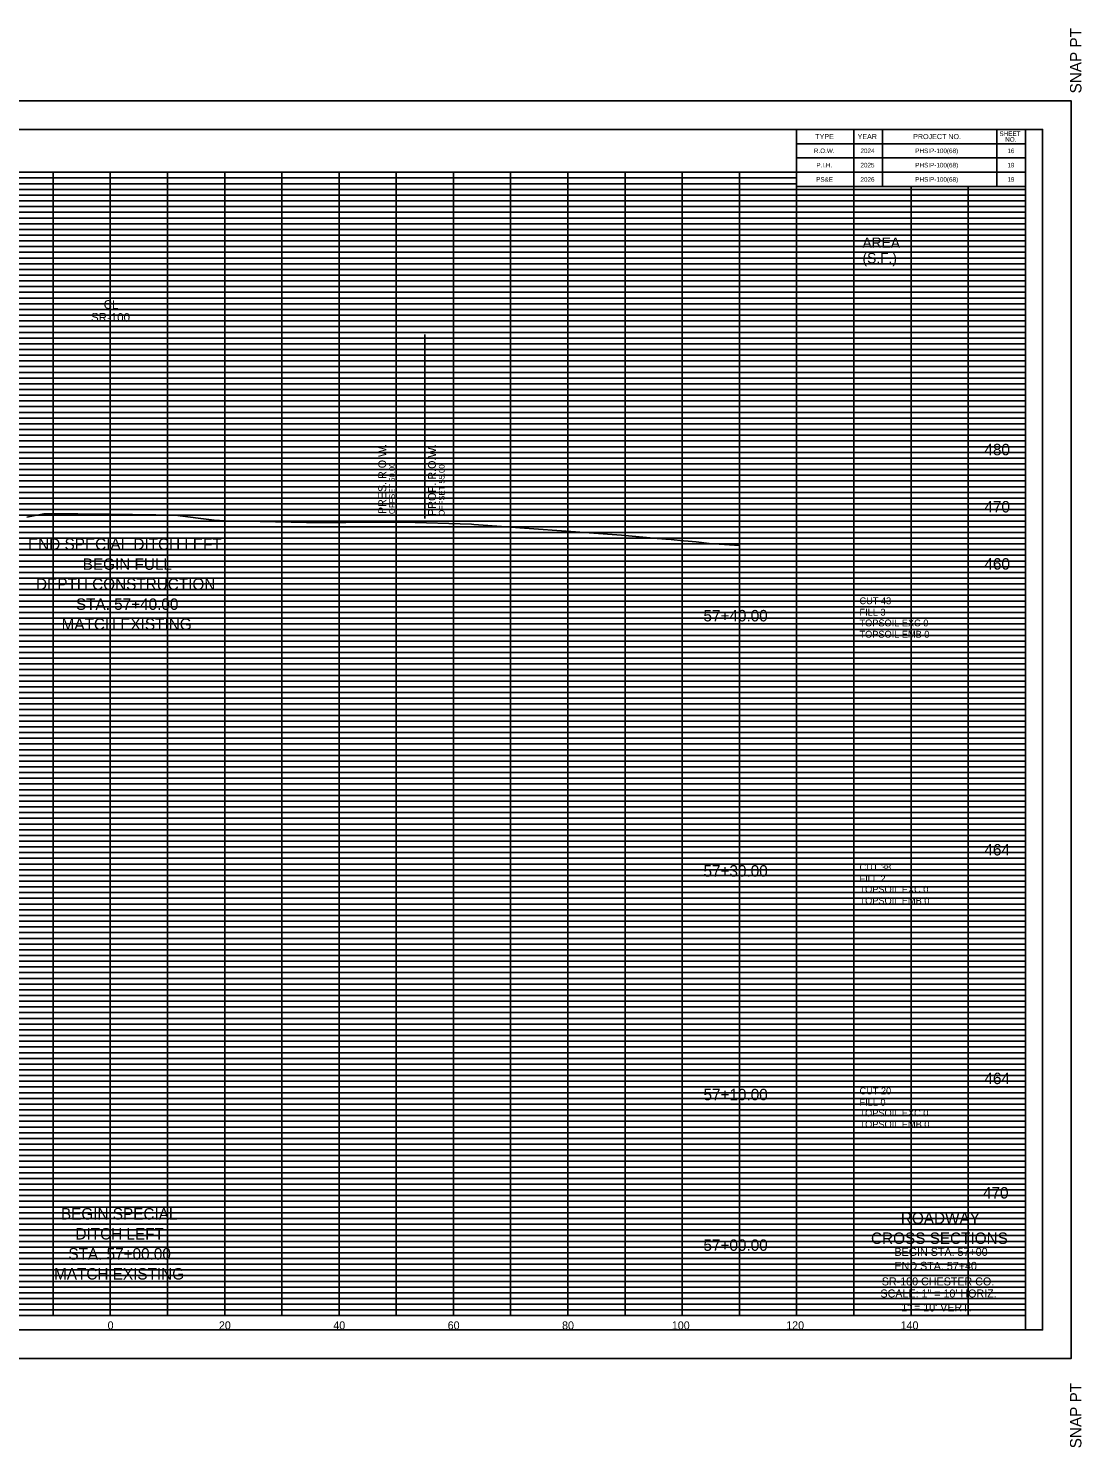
# Model space of a CAD drawing. Extents: x 37 to 1710, y 707 to 2305.
# Drawn here: x 1145.7 to 1329.8, y 706.9 to 955.2 of the extents above; entities that cross this region are included whole.
import ezdxf

# ---------------------------------------------------------------- set-up
doc = ezdxf.new("R2010")
doc.units = 0
for name, color, linetype in [('DESIGN - DRAINAGE - Special Ditch Width Text', 7, 'Continuous'), ('DESIGN - ROW - Right-of-Way Linework', 7, 'Continuous'), ('DESIGN - SCRATCH - User 1', 7, 'Continuous'), ('DESIGN - SHEET - Corner Text', 7, 'Continuous'), ('DESIGN - SHEET - Light Grid', 7, 'Continuous'), ('DESIGN - SHEET - Linework', 7, 'Continuous'), ('DESIGN - SHEET - Plot Shape', 7, 'Continuous'), ('DESIGN - TYPICAL - Text', 7, 'Continuous'), ('SURVEY - GROUND - Top of Ground', 7, 'Continuous'), ('SURVEY - PROPERTY - ROW Lines', 7, 'Continuous'), ('SURVEY - PROPERTY - ROW Lines Text', 7, 'Continuous')]:
    doc.layers.add(name, color=color, linetype=linetype)

msp = doc.modelspace()

# ---------------------------------------------------------------- linework, layer by layer
at = {"layer": 'DESIGN - ROW - Right-of-Way Linework'}
msp.add_line((1215, 869.46), (1215, 901.61), dxfattribs=at)
at = {"layer": 'DESIGN - SCRATCH - User 1'}
for p, q in [((1285, 933.75), (1285, 933.75)), ((1292.5, 933.75), (1292.5, 933.75)), ((1305, 933.75), (1305, 933.75)), ((1317.5, 933.75), (1317.5, 933.75)), ((1285, 931.25), (1285, 931.25)), ((1292.5, 931.25), (1292.5, 931.25)), ((1305, 931.25), (1305, 931.25)), ((1317.5, 931.25), (1317.5, 931.25))]:
    msp.add_line(p, q, dxfattribs=at)
at = {"layer": 'DESIGN - SHEET - Light Grid'}
for p, q in [((1000, 929), (1280, 929)), ((1000, 928), (1280, 928)), ((1000, 927), (1320, 927)), ((1000, 926), (1320, 926)), ((1000, 925), (1320, 925)), ((1000, 924), (1320, 924)), ((1000, 923), (1320, 923)), ((1000, 922), (1320, 922)), ((1000, 921), (1320, 921)), ((1000, 919), (1320, 919)), ((1000, 918), (1320, 918)), ((1000, 917), (1320, 917)), ((1000, 916), (1320, 916)), ((1000, 915), (1320, 915)), ((1000, 914), (1320, 914)), ((1000, 913), (1320, 913)), ((1000, 912), (1320, 912)), ((1000, 911), (1320, 911)), ((1000, 909), (1320, 909)), ((1000, 908), (1320, 908)), ((1000, 907), (1320, 907)), ((1000, 906), (1320, 906)), ((1000, 905), (1320, 905)), ((1000, 904), (1320, 904)), ((1000, 903), (1320, 903)), ((1000, 902), (1320, 902)), ((1000, 901), (1320, 901)), ((1000, 899), (1320, 899)), ((1000, 898), (1320, 898)), ((1000, 897), (1320, 897)), ((1000, 896), (1320, 896)), ((1000, 895), (1320, 895)), ((1000, 894), (1320, 894)), ((1000, 893), (1320, 893)), ((1000, 892), (1320, 892)), ((1000, 891), (1320, 891)), ((1000, 889), (1320, 889)), ((1000, 888), (1320, 888)), ((1000, 887), (1320, 887)), ((1000, 886), (1320, 886)), ((1000, 885), (1320, 885)), ((1000, 884), (1320, 884)), ((1000, 883), (1320, 883)), ((1000, 882), (1320, 882)), ((1000, 881), (1320, 881)), ((1000, 879), (1320, 879)), ((1000, 878), (1320, 878)), ((1000, 877), (1320, 877)), ((1000, 876), (1320, 876)), ((1000, 875), (1320, 875)), ((1000, 874), (1320, 874)), ((1000, 873), (1320, 873)), ((1000, 872), (1320, 872)), ((1000, 871), (1320, 871)), ((1000, 869), (1320, 869)), ((1000, 868), (1320, 868)), ((1000, 867), (1320, 867)), ((1000, 866), (1320, 866)), ((1000, 865), (1320, 865)), ((1000, 864), (1320, 864)), ((1000, 863), (1320, 863)), ((1000, 862), (1320, 862)), ((1000, 861), (1320, 861)), ((1000, 859), (1320, 859)), ((1000, 858), (1320, 858)), ((1000, 857), (1320, 857)), ((1000, 856), (1320, 856)), ((1000, 855), (1320, 855)), ((1000, 854), (1320, 854)), ((1000, 853), (1320, 853)), ((1000, 852), (1320, 852)), ((1000, 851), (1320, 851)), ((1000, 849), (1320, 849)), ((1000, 848), (1320, 848)), ((1000, 847), (1320, 847)), ((1000, 846), (1320, 846)), ((1000, 845), (1320, 845)), ((1000, 844), (1320, 844)), ((1000, 843), (1320, 843)), ((1000, 842), (1320, 842)), ((1000, 841), (1320, 841)), ((1000, 839), (1320, 839)), ((1000, 838), (1320, 838)), ((1000, 837), (1320, 837)), ((1000, 836), (1320, 836)), ((1000, 835), (1320, 835)), ((1000, 834), (1320, 834)), ((1000, 833), (1320, 833)), ((1000, 832), (1320, 832)), ((1000, 831), (1320, 831)), ((1000, 829), (1320, 829)), ((1000, 828), (1320, 828)), ((1000, 827), (1320, 827)), ((1000, 826), (1320, 826)), ((1000, 825), (1320, 825)), ((1000, 824), (1320, 824)), ((1000, 823), (1320, 823)), ((1000, 822), (1320, 822)), ((1000, 821), (1320, 821)), ((1000, 819), (1320, 819)), ((1000, 818), (1320, 818)), ((1000, 817), (1320, 817)), ((1000, 816), (1320, 816)), ((1000, 815), (1320, 815)), ((1000, 814), (1320, 814)), ((1000, 813), (1320, 813)), ((1000, 812), (1320, 812)), ((1000, 811), (1320, 811)), ((1000, 809), (1320, 809)), ((1000, 808), (1320, 808)), ((1000, 807), (1320, 807)), ((1000, 806), (1320, 806)), ((1000, 805), (1320, 805)), ((1000, 804), (1320, 804)), ((1000, 803), (1320, 803)), ((1000, 802), (1320, 802)), ((1000, 801), (1320, 801)), ((1000, 799), (1320, 799)), ((1000, 798), (1320, 798)), ((1000, 797), (1320, 797)), ((1000, 796), (1320, 796)), ((1000, 795), (1320, 795)), ((1000, 794), (1320, 794)), ((1000, 793), (1320, 793)), ((1000, 792), (1320, 792)), ((1000, 791), (1320, 791)), ((1000, 789), (1320, 789)), ((1000, 788), (1320, 788)), ((1000, 787), (1320, 787)), ((1000, 786), (1320, 786)), ((1000, 785), (1320, 785)), ((1000, 784), (1320, 784)), ((1000, 783), (1320, 783)), ((1000, 782), (1320, 782)), ((1000, 781), (1320, 781)), ((1000, 779), (1320, 779)), ((1000, 778), (1320, 778)), ((1000, 777), (1320, 777)), ((1000, 776), (1320, 776)), ((1000, 775), (1320, 775)), ((1000, 774), (1320, 774)), ((1000, 773), (1320, 773)), ((1000, 772), (1320, 772)), ((1000, 771), (1320, 771)), ((1000, 769), (1320, 769)), ((1000, 768), (1320, 768)), ((1000, 767), (1320, 767)), ((1000, 766), (1320, 766)), ((1000, 765), (1320, 765)), ((1000, 764), (1320, 764)), ((1000, 763), (1320, 763)), ((1000, 762), (1320, 762)), ((1000, 761), (1320, 761)), ((1000, 759), (1320, 759)), ((1000, 758), (1320, 758)), ((1000, 757), (1320, 757)), ((1000, 756), (1320, 756)), ((1000, 755), (1320, 755)), ((1000, 754), (1320, 754)), ((1000, 753), (1320, 753)), ((1000, 752), (1320, 752)), ((1000, 751), (1320, 751)), ((1000, 749), (1320, 749)), ((1000, 748), (1320, 748)), ((1000, 747), (1320, 747)), ((1000, 746), (1320, 746)), ((1000, 745), (1320, 745)), ((1000, 744), (1320, 744)), ((1000, 743), (1320, 743)), ((1000, 742), (1320, 742)), ((1000, 741), (1320, 741)), ((1000, 739), (1320, 739)), ((1000, 738), (1320, 738)), ((1000, 737), (1320, 737)), ((1000, 736), (1320, 736)), ((1000, 735), (1320, 735)), ((1000, 734), (1320, 734)), ((1000, 733), (1320, 733)), ((1000, 732), (1320, 732)), ((1000, 731), (1320, 731))]:
    msp.add_line(p, q, dxfattribs=at)
at = {"layer": 'DESIGN - SHEET - Linework'}
for p, q in [((1320, 937.5), (1280, 937.5)), ((1280, 930), (1280, 937.5)), ((1290, 930), (1290, 937.5)), ((1295, 927.5), (1295, 937.5)), ((1315, 927.5), (1315, 937.5)), ((1320, 930), (1320, 937.5)), ((1320, 935), (1280, 935)), ((1320, 932.5), (1280, 932.5)), ((1000, 930), (1320, 930)), ((1150, 730), (1150, 930)), ((1160, 730), (1160, 930)), ((1170, 730), (1170, 930)), ((1180, 730), (1180, 930)), ((1190, 730), (1190, 930)), ((1200, 730), (1200, 930)), ((1210, 730), (1210, 930)), ((1220, 730), (1220, 930)), ((1230, 730), (1230, 930)), ((1240, 730), (1240, 930)), ((1250, 730), (1250, 930)), ((1260, 730), (1260, 930)), ((1270, 730), (1270, 930)), ((1280, 730), (1280, 930)), ((1290, 730), (1290, 930)), ((1320, 927.5), (1280, 927.5)), ((1300, 730), (1300, 927.5)), ((1310, 730), (1310, 927.5)), ((1000, 920), (1320, 920)), ((1000, 910), (1320, 910)), ((1000, 900), (1320, 900)), ((1000, 890), (1320, 890)), ((1000, 880), (1320, 880)), ((1000, 870), (1320, 870)), ((1000, 860), (1320, 860)), ((1000, 850), (1320, 850)), ((1000, 840), (1320, 840)), ((1000, 830), (1320, 830)), ((1000, 820), (1320, 820)), ((1000, 810), (1320, 810)), ((1000, 800), (1320, 800)), ((1000, 790), (1320, 790)), ((1000, 780), (1320, 780)), ((1000, 770), (1320, 770)), ((1000, 760), (1320, 760)), ((1000, 750), (1320, 750)), ((1000, 740), (1320, 740)), ((1000, 730), (1320, 730))]:
    msp.add_line(p, q, dxfattribs=at)
for points in [[(988, 942.5), (1328, 942.5), (1328, 722.5), (988, 722.5)], [(1000, 937.5), (1320, 937.5), (1320, 727.5), (1000, 727.5)]]:
    msp.add_lwpolyline(points, close=True, dxfattribs=at)
at = {"layer": 'DESIGN - SHEET - Plot Shape'}
msp.add_lwpolyline([(993, 937.5), (1323, 937.5), (1323, 727.5), (993, 727.5)], close=True, dxfattribs=at)
at = {"layer": 'SURVEY - GROUND - Top of Ground'}
msp.add_line((1223.55, 868.4), (1249.38, 866.5), dxfattribs=at)
for points in [[(1145.43, 869.65), (1148.36, 870.25), (1154.31, 870.23), (1159.78, 870.22), (1167.94, 870.06), (1171.32, 870), (1175.37, 869.5), (1178.17, 869.15), (1180.96, 869), (1186.18, 868.91), (1194.32, 868.74), (1197.76, 868.75), (1201.18, 868.76), (1204.58, 868.77), (1207.96, 868.78), (1211.32, 868.79), (1223.15, 868.42), (1223.55, 868.4)], [(1249.38, 866.5), (1255.63, 865.94), (1256.46, 865.87), (1257.16, 865.82), (1258.05, 865.74), (1260.21, 865.54), (1261.02, 865.47), (1262.46, 865.33), (1264.7, 865.09), (1270, 864.7)]]:
    msp.add_lwpolyline(points, dxfattribs=at)
at = {"layer": 'SURVEY - PROPERTY - ROW Lines'}
for p, q in [((1210, 891.74), (1210, 901.74)), ((1210, 880.74), (1210, 890.74)), ((1210, 869.74), (1210, 879.74))]:
    msp.add_line(p, q, dxfattribs=at)

# ---------------------------------------------------------------- texts
at = {"layer": 'DESIGN - DRAINAGE - Special Ditch Width Text'}
for s, p in [('CL', (1158.85, 906.13)), ('SR-100', (1156.64, 903.89))]:
    msp.add_text(s, height=1.5, rotation=359.6675, dxfattribs=at).set_placement(p)
at = {"layer": 'DESIGN - ROW - Right-of-Way Linework'}
for s, height, p in [('PROP. R.O.W.', 1.4, (1216.95, 869.9)), ('OFFSET 55.00', 1, (1218.45, 869.9))]:
    msp.add_text(s, height=height, rotation=90, dxfattribs=at).set_placement(p)
at = {"layer": 'DESIGN - SHEET - Corner Text'}
for s, p in [('  SNAP PT', (1329.8, 942.3)), ('SNAP PT  ', (1329.8, 706.8))]:
    msp.add_text(s, height=2, rotation=90, dxfattribs=at).set_placement(p)
for s, height, p in [('R.O.W.', 0.8, (1283.02, 933.35)), ('2024', 0.8, (1291.16, 933.35)), ('PHSIP-100(68)', 0.8, (1300.75, 933.35)), ('16', 0.8, (1316.86, 933.35)), ('P.I.H.', 0.8, (1283.45, 930.85)), ('2025', 0.8, (1291.16, 930.85)), ('PHSIP-100(68)', 0.8, (1300.75, 930.85)), ('19', 0.8, (1316.86, 930.85)), ('PS&E', 0.8, (1283.42, 928.35)), ('2026', 0.8, (1291.16, 928.35)), ('PHSIP-100(68)', 0.8, (1300.75, 928.35)), ('19', 0.8, (1316.86, 928.35)), ('ROADWAY ', 2, (1298.23, 746.05)), ('CROSS SECTIONS', 2, (1293.01, 742.55)), ('BEGIN STA. 57+00', 1.4, (1297.11, 740.46)), ('END STA. 57+40', 1.4, (1297.11, 738.01)), ('SR-100 CHESTER CO.', 1.4, (1294.89, 735.29)), ('SCALE: 1" = 10\' HORIZ.', 1.4, (1294.66, 733.18)), ('       1" = 10\' VERT.   ', 1.4, (1294.66, 730.73))]:
    msp.add_text(s, height=height, dxfattribs=at).set_placement(p)
at = {"layer": 'DESIGN - SHEET - Light Grid'}
for s, height, p in [('TYPE', 0.9, (1283.26, 935.8)), ('YEAR', 0.9, (1290.66, 935.8)), ('PROJECT NO.', 0.9, (1300.38, 935.8)), ('SHEET', 0.8, (1315.47, 936.35)), ('NO.', 0.8, (1316.47, 935.35))]:
    msp.add_text(s, height=height, dxfattribs=at).set_placement(p)
at = {"layer": 'DESIGN - TYPICAL - Text'}
for s, height, p in [('AREA ', 1.8, (1291.52, 916.79)), ('(S.F.)', 1.8, (1291.52, 914.09)), ('480', 2, (1312.84, 880.5)), ('470', 2, (1312.84, 870.5)), ('END SPECIAL DITCH LEFT', 2, (1145.61, 863.96)), ('BEGIN FULL ', 2, (1155.18, 860.46)), ('460', 2, (1312.84, 860.5)), ('DEPTH CONSTRUCTION', 2, (1147.02, 856.96)), ('STA. 57+40.00', 2, (1153.99, 853.46)), ('CUT 43', 1.2, (1291, 854.44)), ('MATCH EXISTING', 2, (1151.49, 849.96)), ('     57+40.00     ', 2, (1260, 851.44)), ('TOPSOIL EXC 0', 1.2, (1291, 850.57)), ('FILL 3', 1.2, (1291, 852.44)), ('TOPSOIL EMB 0', 1.2, (1291, 848.59)), ('464', 2, (1312.84, 810.5)), ('     57+30.00     ', 2, (1260, 806.8)), ('CUT 38', 1.2, (1291, 807.84)), ('FILL 2', 1.2, (1291, 805.84)), ('TOPSOIL EXC 0', 1.2, (1291, 803.97)), ('TOPSOIL EMB 0', 1.2, (1291, 801.99)), ('464', 2, (1312.84, 770.5)), ('     57+10.00     ', 2, (1260, 767.68)), ('CUT 20', 1.2, (1291, 768.72)), ('FILL 0', 1.2, (1291, 766.72)), ('TOPSOIL EXC 0', 1.2, (1291, 764.85)), ('TOPSOIL EMB 0', 1.2, (1291, 762.87)), ('     470     ', 2, (1308.87, 750.49)), ('BEGIN SPECIAL ', 2, (1151.37, 746.82)), ('DITCH LEFT', 2, (1153.91, 743.32)), ('     57+00.00     ', 2, (1260, 741.34)), ('STA. 57+00.00', 2, (1152.67, 739.82)), ('MATCH EXISTING', 2, (1150.17, 736.32)), ('     0     ', 1.4, (1156.93, 727.6)), ('     0     ', 1.4, (1156.93, 727.6)), ('     20     ', 1.4, (1176.39, 727.6)), ('     40     ', 1.4, (1196.39, 727.6)), ('     60     ', 1.4, (1216.39, 727.6)), ('     80     ', 1.4, (1236.39, 727.6)), ('     100     ', 1.4, (1255.58, 727.6)), ('     120     ', 1.4, (1275.58, 727.6)), ('     140     ', 1.4, (1295.58, 727.6))]:
    msp.add_text(s, height=height, dxfattribs=at).set_placement(p)
at = {"layer": 'SURVEY - PROPERTY - ROW Lines Text'}
for s, height, p in [('PRES. R.O.W.', 1.4, (1208.25, 870.22)), ('OFFSET 50.00', 1, (1209.75, 870.22))]:
    msp.add_text(s, height=height, rotation=90, dxfattribs=at).set_placement(p)

doc.saveas('drawing.dxf')
